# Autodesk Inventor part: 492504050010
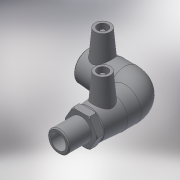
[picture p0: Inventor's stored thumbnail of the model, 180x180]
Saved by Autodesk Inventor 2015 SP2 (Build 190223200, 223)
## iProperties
Created: 2017-06
Part Number: 492504050010
Material: Generic
Description: PLASSON 90° ELBOW MALE TRANSITION 50-1"
Document SubType Name: Modeling
Designer: KIM
Mass: 286.744 g
Surface Area: 655.502 cm^2
Volume: 286.744 cm^3
Density: 1 g/cm^3
Appearance: Default
Author: KIM
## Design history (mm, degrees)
derived "492504.ipt"
feature "Solid1::492504.ipt"
tag "TaggingFeature1"
body "Solid1"
other parameters: "d2" = 67, "d4" = 36, "d5" = 60.3, "d8" = 168 deg, "d10" = 19.2, "d11" = 6.4, "d29" = 52, "d30" = 15, "d31" = 59.4, "d34" = 5 deg, "d41" = 4, "d42" = 14, "d43" = 0, "d48" = 74.5, "d50" = 42.5, "d51" = 19.2, "d52" = 48, "d54" = 90 deg, "d58" = 48, "d59" = 0, "d61" = 90 deg, "d86" = 3, "d87" = 0, "d93" = 0.1, "d94" = 8.5, "d95" = 33.249, "d96" = 23.2743, "d97" = 38, "d98" = 34, "d99" = 67, "d100" = 30.6, "d102" = 2.5, "d106" = 0, "L_" = 142, "L_1" = 48, "D_" = 38, "A_" = 52, "d_2" = 12, "L_2" = 34, "D_1" = 67, "R_" = 33.249
